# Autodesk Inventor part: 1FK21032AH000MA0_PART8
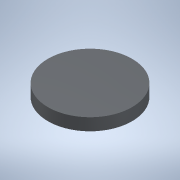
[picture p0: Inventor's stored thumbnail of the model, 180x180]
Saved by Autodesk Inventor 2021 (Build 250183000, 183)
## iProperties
Created: 2025-04
Part Number: 1FK21032AH000MA0_PART8
Material: Generic
Catalog Web Link: www.3dfindit.com
Description: -Servo synchronous motor
Document SubType Name: Modeling
Designer: psAdmin
Mass: 0.299142 g
Surface Area: 3.8585 cm^2
Volume: 0.299142 cm^3
Density: 1 g/cm^3
Appearance: PSOLRGB-38-46-56
Category: PARTsolutions
Title: 1FK21032AH000MA0_PART8
Author: Cadenas PARTsolutions
Comments: Servo synchronous motor
Sending System: PARTsolutions
Preprocessor: ST-DEVELOPER v19.3
PSOL_IDENT_0: {$CADENAS_DATA/23d-libs/siemens_ag/_cat_/45/10/1fk21032ah000ma0.prj},213 {VTYP=3D},{NB=1FK21032AH000
PSOL_IDENT_1: MA0_PART8},{LINA=1FK21032AH000MA0_PART8},{NN=1FK21032AH000MA0_PART8},{NOPRJ=TRUE},{DATE=19.08.2025 1
PSOL_IDENT_2: 4:00:35},{GEOMDATE=30.07.2025 02:02:03},{VERSION=},{LINEID=10},{WBVAR=},{WBNUMERIC=}  {NB=1FK21032AH
PSOL_IDENT_3: 000MA0_PART8},{LINA=1FK21032AH000MA0_PART8},{KT=DUMMY},{PREVIEW=../../../_pool_/14/8e/p_d211_xx_0042
PSOL_IDENT_4: 6j.png},{DESCSHORT=SIMOTICS S-1FK2 HD, SINAMICS S210 3AC 400V-480V, 0.59 Nm, 4500 rpm},{DESCLONG=SIM
PSOL_IDENT_5: OTICS S-1FK2 HD servo motor M0=0.64 Nm; PN = 0.28 kW at nN=4500 rpm (380-480 V); PN = 0.167 kW at nN=
PSOL_IDENT_6: 2500 rpm (200-240 V); degree of protection IP64; cylindrical shaft D14 x 30 mm; absolute encoder 22-
PSOL_IDENT_7: bit + 12-bit multiturn (encoder AM22DQC); with OCC interface; plug size M17, rotatable; SIMOTICS S-1
PSOL_IDENT_8: FK2 servomotorfor a wide range of uses in industrial environments. SIMOTICS S‑1FK2 servomotors are c
PSOL_IDENT_9: ompact synchronous motors with a high dynamic performance that set themselves apart as a result of t
PSOL_IDENT_10: heir high power density, degree of protection and overload capability. The motors are available in t
PSOL_IDENT_11: wo variants: as High Dynamic variant (highest dynamic performance as a result of the low intrinsic m
PSOL_IDENT_12: oment of inertia for applications demanding a high dynamic performance with low moved masses) - and
PSOL_IDENT_13: as Compact variant (precise and stable closed-loop control for medium up to large moved masses as a
PSOL_IDENT_14: result of a medium intrinsic moment of inertia). SIMOTICSS‑1FK2 servomotors fully exploit their stre
PSOL_IDENT_15: ngths in a system with the SINAMICSS210 frequency converter and simple connection using the one cabl
PSOL_IDENT_16: e connection (OCC). Advantages include the short control and positioning times, fast and precise cor
PSOL_IDENT_17: rection of disturbing quantities as well as stable control with a high dynamic performance. The serv
PSOL_IDENT_18: o motors can be configured to address a wide range of requirements. For example with and without hol
PSOL_IDENT_19: ding brake, IP64 or IP65 degree of protection, singleturn or multiturn absolute encoders - to name j
PSOL_IDENT_20: ust a few. Further, the servomotors are available in different shaft heights extending from 20 to 10
PSOL_IDENT_21: 0. A shaft sealing ring is available to achieve an IP65 degree of protection and for subsequent moun
PSOL_IDENT_22: ting at the motor or as spare part. SIMOTICS - the optimum motor for each and every motion control a
PSOL_IDENT_23: pplication.},{INTNO=195125335004},{SUPPLIERALTNO=1FK2103-2AH00-0MA0},{MANUID=1FK21032AH000MA0},{MANU
PSOL_IDENT_24: NAME=Siemens},{MANUTYPEDESC=SYNCHRONOUS MOTOR 1FK2 HD 0,64 NM},{AAU732=SIMOTICS},{AAO057=S-1FK2},{AA
PSOL_IDENT_25: U734=SIMOTICS S-1FK2 HD servo motor M0=0.64 Nm; PN = 0.28 kW at nN=4500 rpm (380-480 V); PN = 0.167
PSOL_IDENT_26: kW at nN=2500 rpm (200-240 V); degree of protection IP64; cylindrical shaft D14 x 30 mm; absolute en
PSOL_IDENT_27: coder 22-bit + 12-bit multiturn (encoder AM22DQC); with OCC interface; plug size M17, rotatable;},{A
PSOL_IDENT_28: AW338=SYNCHRONOUS MOTOR 1FK2 HD 0,64 NM},{AAO742=SIMOTICS},{AAO663=4034106444624},{NOCUPEROU=1},{PRI
PSOL_IDENT_29: CEQUANTITY=1},{QUANTITYMIN=1},{QUANTITYINT=1},{CTN=85015100},{COO=RO},{AAO676=1FK2103-2AH00-0MA0},{A
PSOL_IDENT_30: AO677=Siemens AG},{ORDERUNIT=C62},{CONTENTUNIT=C62}
NB: 1FK21032AH000MA0_PART8
NT: Servo synchronous motor
NBSYN: $MANUID._PART8
LINA: 1FK21032AH000MA0_PART8
CATALOG: SIEMENS
PREVIEW: ../../../_pool_/14/8e/p_d211_xx_00426j.png
DESCSHORT: SIMOTICS S-1FK2 HD, SINAMICS S210 3AC 400V-480V, 0.59 Nm, 4500 rpm
DESCLONG: SIMOTICS S-1FK2 HD servo motor M0=0.64 Nm; PN = 0.28 kW at nN=4500 rpm (380-480 V); PN = 0.167 kW at nN=2500 rpm (200-240 V); degree of protection IP64; cylindr
INTNO: 195125335004
SUPPLIERALTNO: 1FK2103-2AH00-0MA0
MANUID: 1FK21032AH000MA0
MANUNAME: Siemens
MANUTYPEDESC: SYNCHRONOUS MOTOR 1FK2 HD 0,64 NM
AAU732: SIMOTICS
AAO057: S-1FK2
AAU734: SIMOTICS S-1FK2 HD servo motor M0=0.64 Nm; PN = 0.28 kW at nN=4500 rpm (380-480 V); PN = 0.167 kW at nN=2500 rpm (200-240 V); degree of protection IP64; cylindr
AAW338: SYNCHRONOUS MOTOR 1FK2 HD 0,64 NM
AAO742: SIMOTICS
AAO663: 4034106444624.0
NOCUPEROU: 1
PRICEQUANTITY: 1
QUANTITYMIN: 1
QUANTITYINT: 1
CTN: 85015100
COO: RO
ARTICLENO: 1FK21032AH000MA0_PART8
BOMINFO: 1FK21032AH000MA0_PART8
CREATOR: CADENAS GmbH
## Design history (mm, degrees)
feature "2025_04_17_15_00_20_0728"
body "Solid1"
